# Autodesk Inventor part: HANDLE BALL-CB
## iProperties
Created: 2006-07
Part Number: HANDLE BALL-CB
Material: Steel
Document SubType Name: Modeling
Designer: rollin42
Density: 7.85 g/cm^3
Stock Number: HANDLE BALL-CB
Author: rollin42
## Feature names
1. Revolution1
2. Extrusion1
3. Hole1
